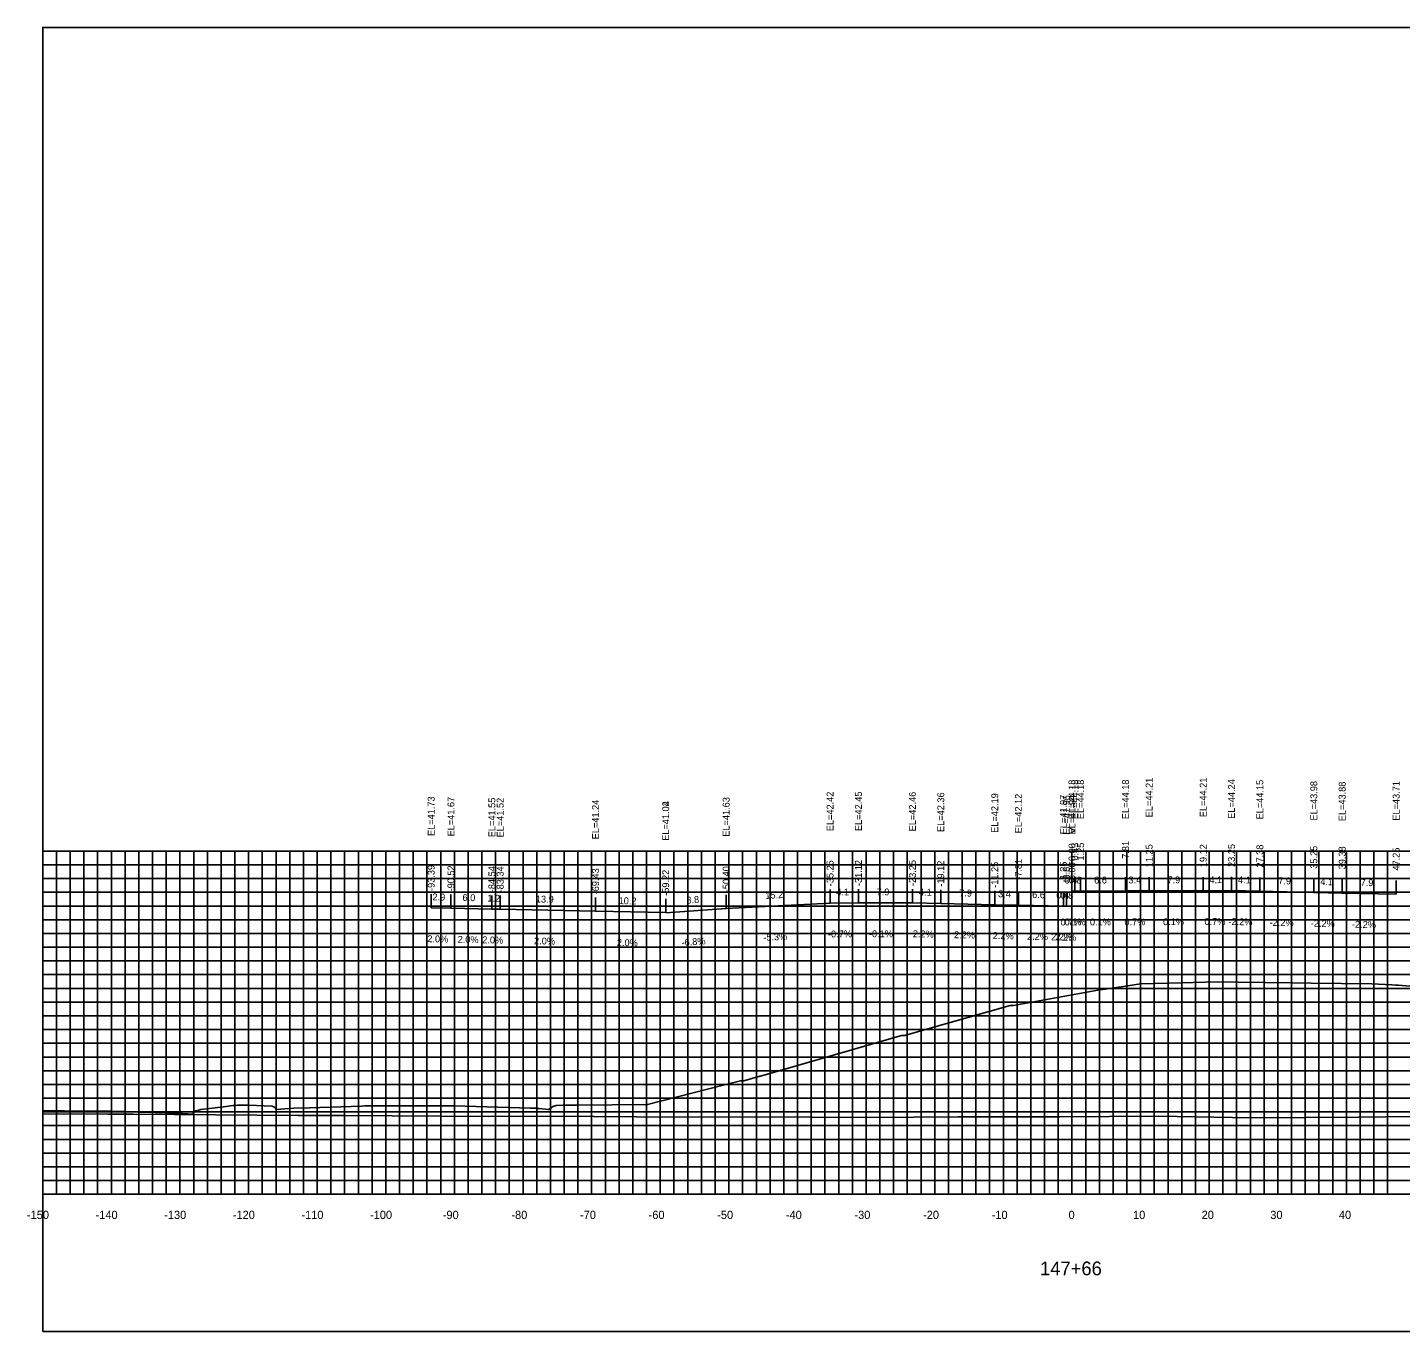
# Model space of a CAD drawing. Extents: x 1800880 to 1818864, y 245271 to 250560.
# Drawn here: x 1808037.4 to 1808237.5, y 248125.1 to 248315.1 of the extents above; entities that cross this region are included whole.
import ezdxf

# ---------------------------------------------------------------- set-up
doc = ezdxf.new("R2010")
doc.units = 0
for name, color, linetype in [('ANNO-TXT', 7, 'Continuous'), ('AXIS', 7, 'Continuous'), ('CL-CNST', 7, 'Continuous'), ('DESIGN - DRAINAGE - Bridges', 7, 'Continuous'), ('Level 32', 7, 'Continuous'), ('Level 37', 7, 'Continuous'), ('Level 46', 7, 'Continuous'), ('Level 62', 7, 'Continuous'), ('SHT-BDR', 7, 'Continuous')]:
    doc.layers.add(name, color=color, linetype=linetype)

msp = doc.modelspace()

# ---------------------------------------------------------------- linework, layer by layer
at = {"layer": 'AXIS'}
msp.add_lwpolyline([(1808189.66, 248189.27), (1808190.09, 248189.27), (1808190.91, 248189.27), (1808197.47, 248189.28), (1808200.91, 248189.3), (1808208.79, 248189.3), (1808212.91, 248189.33), (1808217.04, 248189.24), (1808224.91, 248189.07), (1808229.04, 248188.98), (1808236.91, 248188.8)], dxfattribs=at)
at = {"layer": 'CL-CNST'}
msp.add_lwpolyline([(1808039.66, 248157.24), (1808041.18, 248157.24), (1808042.85, 248157.25), (1808048.88, 248157.19), (1808049.54, 248157.18), (1808050.9, 248157.15), (1808050.96, 248157.15), (1808051.02, 248157.15), (1808051.09, 248157.14), (1808051.17, 248157.14), (1808051.26, 248157.14), (1808051.35, 248157.14), (1808051.46, 248157.13), (1808051.58, 248157.13), (1808051.72, 248157.13), (1808051.88, 248157.12), (1808052.06, 248157.12), (1808052.27, 248157.11), (1808052.51, 248157.1), (1808052.81, 248157.1), (1808053.17, 248157.09), (1808053.61, 248157.07), (1808054.19, 248157.06), (1808054.94, 248157.04), (1808056, 248157.01), (1808057.55, 248156.97), (1808058.85, 248156.93), (1808058.94, 248156.93), (1808059.15, 248156.91), (1808059.32, 248156.9), (1808061.54, 248156.74), (1808061.62, 248156.99), (1808061.9, 248157.27), (1808062.02, 248157.27), (1808062.4, 248157.36), (1808062.71, 248157.45), (1808062.74, 248157.45), (1808066.37, 248157.9), (1808067.35, 248158.03), (1808067.42, 248158.03), (1808067.6, 248158.03), (1808068.02, 248158.05), (1808068.31, 248158.05), (1808068.53, 248158.05), (1808068.97, 248158.05), (1808069.01, 248158.05), (1808069.67, 248158.05), (1808073.1, 248157.91), (1808073.43, 248157.76), (1808073.44, 248157.75), (1808073.46, 248157.74), (1808073.47, 248157.73), (1808073.49, 248157.71), (1808073.5, 248157.7), (1808073.52, 248157.69), (1808073.53, 248157.68), (1808073.54, 248157.67), (1808073.55, 248157.66), (1808073.56, 248157.65), (1808073.57, 248157.65), (1808073.58, 248157.63), (1808073.68, 248157.43), (1808076.27, 248157.66), (1808078.55, 248157.69), (1808086.13, 248157.95), (1808086.61, 248157.98), (1808086.66, 248157.98), (1808087.3, 248157.98), (1808087.64, 248157.99), (1808094.37, 248157.97), (1808099.68, 248157.96), (1808110.7, 248157.65), (1808111.69, 248157.62), (1808111.78, 248157.61), (1808111.86, 248157.6), (1808111.93, 248157.59), (1808112, 248157.58), (1808113.39, 248157.43), (1808113.61, 248157.61), (1808114.01, 248157.9), (1808114.48, 248158.03), (1808115.44, 248158.09), (1808115.45, 248158.09), (1808116.24, 248158.07), (1808117.32, 248158.09), (1808117.69, 248158.09), (1808117.76, 248158.09), (1808127.56, 248158.15), (1808127.82, 248158.15), (1808139.04, 248161.03), (1808141.36, 248161.62), (1808141.44, 248161.62), (1808141.85, 248161.62), (1808144.17, 248162.3), (1808144.28, 248162.3), (1808162.98, 248167.67), (1808164.8, 248168.21), (1808164.9, 248168.21), (1808165.3, 248168.21), (1808167.97, 248169.02), (1808180.67, 248172.61), (1808180.9, 248172.6), (1808181.12, 248172.6), (1808193.43, 248174.83), (1808195.17, 248175.09), (1808197.8, 248175.48), (1808199.65, 248175.76), (1808205.58, 248175.9), (1808210.83, 248176.03), (1808213.88, 248176), (1808221.82, 248175.9), (1808224.5, 248175.87), (1808233.38, 248175.76), (1808236.28, 248175.59), (1808236.87, 248175.55), (1808237.16, 248175.54), (1808237.18, 248175.54), (1808254.24, 248174.12)], dxfattribs=at)
at = {"layer": 'DESIGN - DRAINAGE - Bridges'}
for p, q in [((1808039.6, 248195.09), (1808039.66, 248195.09)), ((1808039.66, 248145.09), (1808039.66, 248195.09)), ((1808039.6, 248185.09), (1808039.66, 248185.09)), ((1808039.6, 248175.09), (1808039.66, 248175.09)), ((1808039.6, 248165.09), (1808039.66, 248165.09)), ((1808039.6, 248155.09), (1808039.66, 248155.09)), ((1808039.6, 248145.09), (1808039.66, 248145.09)), ((1808039.66, 248145.09), (1808339.66, 248145.09)), ((1808039.66, 248145.03), (1808039.66, 248145.09)), ((1808049.66, 248145.03), (1808049.66, 248145.09)), ((1808059.66, 248145.03), (1808059.66, 248145.09)), ((1808069.66, 248145.03), (1808069.66, 248145.09)), ((1808079.66, 248145.03), (1808079.66, 248145.09)), ((1808089.66, 248145.03), (1808089.66, 248145.09)), ((1808099.66, 248145.03), (1808099.66, 248145.09)), ((1808109.66, 248145.03), (1808109.66, 248145.09)), ((1808119.66, 248145.03), (1808119.66, 248145.09)), ((1808129.66, 248145.03), (1808129.66, 248145.09)), ((1808139.66, 248145.03), (1808139.66, 248145.09)), ((1808149.66, 248145.03), (1808149.66, 248145.09)), ((1808159.66, 248145.03), (1808159.66, 248145.09)), ((1808169.66, 248145.03), (1808169.66, 248145.09)), ((1808179.66, 248145.03), (1808179.66, 248145.09)), ((1808189.66, 248145.03), (1808189.66, 248145.09)), ((1808199.66, 248145.03), (1808199.66, 248145.09)), ((1808209.66, 248145.03), (1808209.66, 248145.09)), ((1808219.66, 248145.03), (1808219.66, 248145.09)), ((1808229.66, 248145.03), (1808229.66, 248145.09))]:
    msp.add_line(p, q, dxfattribs=at)
at = {"layer": 'Level 37'}
for p, q in [((1808200.91, 248189.3), (1808200.91, 248191.3)), ((1808208.79, 248189.3), (1808208.79, 248191.3)), ((1808212.91, 248189.33), (1808212.91, 248191.33)), ((1808154.41, 248187.52), (1808154.41, 248189.52)), ((1808158.54, 248187.54), (1808158.54, 248189.54)), ((1808166.41, 248187.55), (1808166.41, 248189.55)), ((1808170.54, 248187.46), (1808170.54, 248189.46)), ((1808189.66, 248189.27), (1808189.66, 248191.27)), ((1808190.09, 248189.27), (1808190.09, 248191.27)), ((1808190.91, 248189.27), (1808190.91, 248191.27)), ((1808197.47, 248189.28), (1808197.47, 248191.28)), ((1808217.04, 248189.24), (1808217.04, 248191.24)), ((1808224.91, 248189.07), (1808224.91, 248191.07)), ((1808229.04, 248188.98), (1808229.04, 248190.98)), ((1808236.91, 248188.8), (1808236.91, 248190.8)), ((1808096.27, 248186.82), (1808096.27, 248188.82)), ((1808099.15, 248186.76), (1808099.15, 248188.76)), ((1808105.12, 248186.64), (1808105.12, 248188.64)), ((1808106.33, 248186.62), (1808106.33, 248188.62)), ((1808120.23, 248186.33), (1808120.23, 248188.33)), ((1808130.45, 248186.13), (1808130.45, 248188.13)), ((1808130.45, 248186.12), (1808130.45, 248188.12)), ((1808139.26, 248186.72), (1808139.26, 248188.72)), ((1808178.41, 248187.28), (1808178.41, 248189.28)), ((1808181.85, 248187.21), (1808181.85, 248189.21)), ((1808188.41, 248187.06), (1808188.41, 248189.06)), ((1808188.84, 248187.05), (1808188.84, 248189.05)), ((1808189.66, 248187.04), (1808189.66, 248189.04))]:
    msp.add_line(p, q, dxfattribs=at)
msp.add_lwpolyline([(1808039.66, 248125.09), (1808339.66, 248125.09), (1808339.66, 248315.09), (1808039.66, 248315.09)], close=True, dxfattribs=at)
at = {"layer": 'Level 46'}
for p, q in [((1808039.66, 248195.09), (1808339.66, 248195.09)), ((1808039.66, 248145.09), (1808039.66, 248195.09)), ((1808041.66, 248145.09), (1808041.66, 248195.09)), ((1808043.66, 248145.09), (1808043.66, 248195.09)), ((1808045.66, 248145.09), (1808045.66, 248195.09)), ((1808047.66, 248145.09), (1808047.66, 248195.09)), ((1808049.66, 248145.09), (1808049.66, 248195.09)), ((1808051.66, 248145.09), (1808051.66, 248195.09)), ((1808053.66, 248145.09), (1808053.66, 248195.09)), ((1808055.66, 248145.09), (1808055.66, 248195.09)), ((1808057.66, 248145.09), (1808057.66, 248195.09)), ((1808059.66, 248145.09), (1808059.66, 248195.09)), ((1808061.66, 248145.09), (1808061.66, 248195.09)), ((1808063.66, 248145.09), (1808063.66, 248195.09)), ((1808065.66, 248145.09), (1808065.66, 248195.09)), ((1808067.66, 248145.09), (1808067.66, 248195.09)), ((1808069.66, 248145.09), (1808069.66, 248195.09)), ((1808071.66, 248145.09), (1808071.66, 248195.09)), ((1808073.66, 248145.09), (1808073.66, 248195.09)), ((1808075.66, 248145.09), (1808075.66, 248195.09)), ((1808077.66, 248145.09), (1808077.66, 248195.09)), ((1808079.66, 248145.09), (1808079.66, 248195.09)), ((1808081.66, 248145.09), (1808081.66, 248195.09)), ((1808083.66, 248145.09), (1808083.66, 248195.09)), ((1808085.66, 248145.09), (1808085.66, 248195.09)), ((1808087.66, 248145.09), (1808087.66, 248195.09)), ((1808089.66, 248145.09), (1808089.66, 248195.09)), ((1808091.66, 248145.09), (1808091.66, 248195.09)), ((1808093.66, 248145.09), (1808093.66, 248195.09)), ((1808095.66, 248145.09), (1808095.66, 248195.09)), ((1808097.66, 248145.09), (1808097.66, 248195.09)), ((1808099.66, 248145.09), (1808099.66, 248195.09)), ((1808101.66, 248145.09), (1808101.66, 248195.09)), ((1808103.66, 248145.09), (1808103.66, 248195.09)), ((1808105.66, 248145.09), (1808105.66, 248195.09)), ((1808107.66, 248145.09), (1808107.66, 248195.09)), ((1808109.66, 248145.09), (1808109.66, 248195.09)), ((1808111.66, 248145.09), (1808111.66, 248195.09)), ((1808113.66, 248145.09), (1808113.66, 248195.09)), ((1808115.66, 248145.09), (1808115.66, 248195.09)), ((1808117.66, 248145.09), (1808117.66, 248195.09)), ((1808119.66, 248145.09), (1808119.66, 248195.09)), ((1808121.66, 248145.09), (1808121.66, 248195.09)), ((1808123.66, 248145.09), (1808123.66, 248195.09)), ((1808125.66, 248145.09), (1808125.66, 248195.09)), ((1808127.66, 248145.09), (1808127.66, 248195.09)), ((1808129.66, 248145.09), (1808129.66, 248195.09)), ((1808131.66, 248145.09), (1808131.66, 248195.09)), ((1808133.66, 248145.09), (1808133.66, 248195.09)), ((1808135.66, 248145.09), (1808135.66, 248195.09)), ((1808137.66, 248145.09), (1808137.66, 248195.09)), ((1808139.66, 248145.09), (1808139.66, 248195.09)), ((1808141.66, 248145.09), (1808141.66, 248195.09)), ((1808143.66, 248145.09), (1808143.66, 248195.09)), ((1808145.66, 248145.09), (1808145.66, 248195.09)), ((1808147.66, 248145.09), (1808147.66, 248195.09)), ((1808149.66, 248145.09), (1808149.66, 248195.09)), ((1808151.66, 248145.09), (1808151.66, 248195.09)), ((1808153.66, 248145.09), (1808153.66, 248195.09)), ((1808155.66, 248145.09), (1808155.66, 248195.09)), ((1808157.66, 248145.09), (1808157.66, 248195.09)), ((1808159.66, 248145.09), (1808159.66, 248195.09)), ((1808161.66, 248145.09), (1808161.66, 248195.09)), ((1808163.66, 248145.09), (1808163.66, 248195.09)), ((1808165.66, 248145.09), (1808165.66, 248195.09)), ((1808167.66, 248145.09), (1808167.66, 248195.09)), ((1808169.66, 248145.09), (1808169.66, 248195.09)), ((1808171.66, 248145.09), (1808171.66, 248195.09)), ((1808173.66, 248145.09), (1808173.66, 248195.09)), ((1808175.66, 248145.09), (1808175.66, 248195.09)), ((1808177.66, 248145.09), (1808177.66, 248195.09)), ((1808179.66, 248145.09), (1808179.66, 248195.09)), ((1808181.66, 248145.09), (1808181.66, 248195.09)), ((1808183.66, 248145.09), (1808183.66, 248195.09)), ((1808185.66, 248145.09), (1808185.66, 248195.09)), ((1808187.66, 248145.09), (1808187.66, 248195.09)), ((1808189.66, 248145.09), (1808189.66, 248195.09)), ((1808191.66, 248145.09), (1808191.66, 248195.09)), ((1808193.66, 248145.09), (1808193.66, 248195.09)), ((1808195.66, 248145.09), (1808195.66, 248195.09)), ((1808197.66, 248145.09), (1808197.66, 248195.09)), ((1808199.66, 248145.09), (1808199.66, 248195.09)), ((1808201.66, 248145.09), (1808201.66, 248195.09)), ((1808203.66, 248145.09), (1808203.66, 248195.09)), ((1808205.66, 248145.09), (1808205.66, 248195.09)), ((1808207.66, 248145.09), (1808207.66, 248195.09)), ((1808209.66, 248145.09), (1808209.66, 248195.09)), ((1808211.66, 248145.09), (1808211.66, 248195.09)), ((1808213.66, 248145.09), (1808213.66, 248195.09)), ((1808215.66, 248145.09), (1808215.66, 248195.09)), ((1808217.66, 248145.09), (1808217.66, 248195.09)), ((1808219.66, 248145.09), (1808219.66, 248195.09)), ((1808221.66, 248145.09), (1808221.66, 248195.09)), ((1808223.66, 248145.09), (1808223.66, 248195.09)), ((1808225.66, 248145.09), (1808225.66, 248195.09)), ((1808227.66, 248145.09), (1808227.66, 248195.09)), ((1808229.66, 248145.09), (1808229.66, 248195.09)), ((1808231.66, 248145.09), (1808231.66, 248195.09)), ((1808233.66, 248145.09), (1808233.66, 248195.09)), ((1808235.66, 248145.09), (1808235.66, 248195.09)), ((1808039.66, 248193.09), (1808339.66, 248193.09)), ((1808039.66, 248191.09), (1808339.66, 248191.09)), ((1808039.66, 248189.09), (1808339.66, 248189.09)), ((1808039.66, 248187.09), (1808339.66, 248187.09)), ((1808039.66, 248185.09), (1808339.66, 248185.09)), ((1808039.66, 248183.09), (1808339.66, 248183.09)), ((1808039.66, 248181.09), (1808339.66, 248181.09)), ((1808039.66, 248179.09), (1808339.66, 248179.09)), ((1808039.66, 248177.09), (1808339.66, 248177.09)), ((1808039.66, 248175.09), (1808339.66, 248175.09)), ((1808039.66, 248173.09), (1808339.66, 248173.09)), ((1808039.66, 248171.09), (1808339.66, 248171.09)), ((1808039.66, 248169.09), (1808339.66, 248169.09)), ((1808039.66, 248167.09), (1808339.66, 248167.09)), ((1808039.66, 248165.09), (1808339.66, 248165.09)), ((1808039.66, 248163.09), (1808339.66, 248163.09)), ((1808039.66, 248161.09), (1808339.66, 248161.09)), ((1808039.66, 248159.09), (1808339.66, 248159.09)), ((1808039.66, 248157.09), (1808339.66, 248157.09)), ((1808039.66, 248155.09), (1808339.66, 248155.09)), ((1808039.66, 248153.09), (1808339.66, 248153.09)), ((1808039.66, 248151.09), (1808339.66, 248151.09)), ((1808039.66, 248149.09), (1808339.66, 248149.09)), ((1808039.66, 248147.09), (1808339.66, 248147.09)), ((1808039.66, 248145.09), (1808339.66, 248145.09))]:
    msp.add_line(p, q, dxfattribs=at)
at = {"layer": 'Level 62'}
for points in [[(1808130.45, 248186.12), (1808139.26, 248186.72), (1808154.41, 248187.52), (1808158.54, 248187.54), (1808166.41, 248187.55), (1808170.54, 248187.46), (1808178.41, 248187.28), (1808181.85, 248187.21), (1808188.41, 248187.06), (1808188.84, 248187.05), (1808189.66, 248187.04)], [(1808096.27, 248186.82), (1808099.15, 248186.76), (1808105.12, 248186.64), (1808106.33, 248186.62), (1808120.23, 248186.33), (1808130.45, 248186.13)], [(1808039.66, 248156.83), (1808049.13, 248156.75), (1808052.85, 248156.74), (1808076.88, 248156.58), (1808083.56, 248156.58), (1808104.64, 248156.43), (1808113.75, 248156.45), (1808132.39, 248156.32), (1808143.56, 248156.35), (1808160.15, 248156.3), (1808173.07, 248156.36), (1808187.9, 248156.38), (1808202.34, 248156.46), (1808215.66, 248156.23), (1808231.41, 248156.32), (1808243.42, 248156.45), (1808254.48, 248156.38), (1808271.17, 248156.48), (1808281.98, 248156.66), (1808298.93, 248156.76), (1808309.43, 248156.48), (1808326.68, 248156.59), (1808339.66, 248156.14)]]:
    msp.add_lwpolyline(points, dxfattribs=at)

# ---------------------------------------------------------------- texts
for s, p in [('-150', (1808037.36, 248141.49)), ('-140', (1808047.36, 248141.49)), ('-130', (1808057.36, 248141.49)), ('-120', (1808067.36, 248141.49)), ('-110', (1808077.36, 248141.49)), ('-100', (1808087.36, 248141.49)), ('-90', (1808097.96, 248141.49)), ('-80', (1808107.96, 248141.49)), ('-70', (1808117.96, 248141.49)), ('-60', (1808127.96, 248141.49)), ('-50', (1808137.96, 248141.49)), ('-40', (1808147.96, 248141.49)), ('-30', (1808157.96, 248141.49)), ('-20', (1808167.96, 248141.49)), ('-10', (1808177.96, 248141.49)), ('0', (1808189.16, 248141.49)), ('10', (1808198.56, 248141.49)), ('20', (1808208.56, 248141.49)), ('30', (1808218.56, 248141.49)), ('40', (1808228.56, 248141.49))]:
    msp.add_text(s, height=1.2).set_placement(p)
at = {"layer": 'ANNO-TXT'}
for s, rotation, p in [('0.4', 0.3792, (1808188.59, 248190.36)), ('0.8', 0.0387, (1808189.22, 248190.37)), ('6.6', 0.0387, (1808192.89, 248190.37)), ('3.4', 0.3792, (1808197.9, 248190.38)), ('7.9', 0.0387, (1808203.57, 248190.4)), ('4.1', 0.3792, (1808209.69, 248190.41)), ('4.1', 358.7397, (1808213.85, 248190.41)), ('4.1', 0.3792, (1808155.31, 248188.62)), ('7.9', 0.0387, (1808161.19, 248188.64)), ('4.1', 358.7397, (1808167.35, 248188.63)), ('7.9', 358.7397, (1808173.22, 248188.5)), ('3.4', 358.7397, (1808178.88, 248188.37)), ('7.9', 358.7397, (1808219.72, 248190.28)), ('4.1', 358.7397, (1808225.85, 248190.15)), ('7.9', 358.7397, (1808231.72, 248190.02)), ('2.9', 358.8438, (1808096.45, 248187.92)), ('6.0', 358.8394, (1808100.83, 248187.83)), ('1.2', 358.8394, (1808104.46, 248187.75)), ('13.9', 358.8394, (1808111.52, 248187.61)), ('10.2', 358.8394, (1808123.58, 248187.37)), ('8.8', 3.9121, (1808133.5, 248187.43)), ('15.2', 3.0056, (1808145, 248188.12)), ('6.6', 358.7397, (1808183.85, 248188.26)), ('0.4', 358.7397, (1808187.37, 248188.19)), ('0.8', 358.7397, (1808187.99, 248188.17)), ('0.7%', 0.3792, (1808197.31, 248184.28)), ('0.1%', 0.0387, (1808202.94, 248184.3)), ('0.7%', 0.3792, (1808208.97, 248184.31)), ('-2.2%', 358.7397, (1808212.46, 248184.34)), ('-0.7%', 0.3792, (1808154.1, 248182.51)), ('-0.1%', 0.0387, (1808160.07, 248182.54)), ('2.2%', 358.7397, (1808166.46, 248182.55)), ('2.2%', 358.7397, (1808172.46, 248182.41)), ('2.2%', 358.7397, (1808178.11, 248182.29)), ('0.7%', 0.3792, (1808188, 248184.26)), ('0.1%', 0.0387, (1808188.59, 248184.27)), ('0.1%', 0.0387, (1808192.28, 248184.27)), ('-2.2%', 358.7397, (1808218.46, 248184.21)), ('-2.2%', 358.7397, (1808224.46, 248184.08)), ('-2.2%', 358.7397, (1808230.46, 248183.94)), ('2.0%', 358.8438, (1808095.7, 248181.83)), ('2.0%', 358.8394, (1808100.12, 248181.74)), ('2.0%', 358.8394, (1808103.71, 248181.67)), ('2.0%', 358.8394, (1808111.26, 248181.52)), ('2.0%', 358.8394, (1808123.33, 248181.27)), ('-6.8%', 3.9121, (1808132.79, 248181.27)), ('-5.3%', 3.0056, (1808144.69, 248182)), ('2.2%', 358.7397, (1808183.11, 248182.18)), ('2.2%', 358.7397, (1808186.61, 248182.1)), ('2.2%', 358.7397, (1808187.23, 248182.09))]:
    msp.add_text(s, height=1, rotation=rotation, dxfattribs=at).set_placement(p)
at = {"layer": 'DESIGN - DRAINAGE - Bridges'}
for s, height, p in [('>', 1.5, (1808189.06, 248197.34)), ('-', 0.0001, (1808039.66, 248145.09))]:
    msp.add_text(s, height=height, dxfattribs=at).set_placement(p)
at = {"layer": 'Level 32'}
msp.add_text('147+66', height=2, dxfattribs=at).set_placement((1808185.01, 248133.29))
at = {"layer": 'SHT-BDR'}
for s, p in [('EL=44.18', (1808190.16, 248199.74)), ('EL=44.18', (1808190.59, 248199.74)), ('EL=44.18', (1808191.41, 248199.74)), ('EL=44.18', (1808197.97, 248199.75)), ('EL=44.21', (1808201.41, 248200.02)), ('EL=44.21', (1808209.29, 248200.03)), ('EL=44.24', (1808213.41, 248199.8)), ('EL=44.15', (1808217.54, 248199.71)), ('EL=42.42', (1808154.91, 248197.99)), ('EL=42.45', (1808159.04, 248198.01)), ('EL=42.46', (1808166.91, 248197.97)), ('EL=42.36', (1808171.04, 248197.88)), ('EL=42.19', (1808178.91, 248197.76)), ('EL=42.12', (1808182.35, 248197.68)), ('EL=43.98', (1808225.41, 248199.54)), ('EL=43.88', (1808229.54, 248199.45)), ('EL=43.71', (1808237.41, 248199.53)), ('EL=41.73', (1808096.77, 248197.29)), ('EL=41.67', (1808099.65, 248197.23)), ('EL=41.55', (1808105.62, 248197.11)), ('EL=41.52', (1808106.83, 248197.09)), ('EL=41.24', (1808120.73, 248196.81)), ('EL=41.04', (1808130.95, 248196.6)), ('EL=41.02', (1808130.95, 248196.59)), ('EL=41.63', (1808139.76, 248197.19)), ('EL=41.97', (1808188.91, 248197.54)), ('EL=41.96', (1808189.34, 248197.48)), ('EL=41.94', (1808190.16, 248197.51)), ('0.00', (1808190.16, 248193.63)), ('0.43', (1808190.59, 248193.71)), ('1.25', (1808191.41, 248193.71)), ('7.81', (1808197.97, 248193.97)), ('11.25', (1808201.41, 248192.75)), ('19.12', (1808209.29, 248192.75)), ('23.25', (1808213.41, 248192.78)), ('27.38', (1808217.54, 248192.69)), ('35.25', (1808225.41, 248192.52)), ('39.38', (1808229.54, 248192.43)), ('47.25', (1808237.41, 248192.25)), ('-35.25', (1808154.91, 248189.97)), ('-31.12', (1808159.04, 248190)), ('-23.25', (1808166.91, 248190)), ('-19.12', (1808171.04, 248189.91)), ('-11.25', (1808178.91, 248189.74)), ('-7.81', (1808182.35, 248190.91)), ('-1.25', (1808188.91, 248190.51)), ('-0.82', (1808189.34, 248190.5)), ('-0.00', (1808190.16, 248190.41)), ('-93.39', (1808096.77, 248189.28)), ('-90.52', (1808099.65, 248189.22)), ('-84.54', (1808105.62, 248189.1)), ('-83.34', (1808106.83, 248189.07)), ('-69.43', (1808120.73, 248188.79)), ('-59.22', (1808130.95, 248188.58)), ('-59.22', (1808130.95, 248188.57)), ('-50.40', (1808139.76, 248189.1))]:
    msp.add_text(s, height=1, rotation=90, dxfattribs=at).set_placement(p)

doc.saveas('drawing.dxf')
